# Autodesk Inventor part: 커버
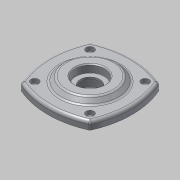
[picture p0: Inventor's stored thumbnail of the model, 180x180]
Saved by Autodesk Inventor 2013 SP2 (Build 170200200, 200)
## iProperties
Created: 2016-05
Part Number: 커버
Document SubType Name: Modeling
Designer: mduedu
Density: 2.71 g/cm^3
Material: 알루미늄 6061
Author: mduedu
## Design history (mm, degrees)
sketch "스케치1"
  geometry: L1 (0, 0)-(-35.355, 35.355); L2 (0, 0)-(0, 43); L3 (0, 0)-(43, 0); C1 r 25 at (0, 0); A1 r 85.579 centre (0, -42.579) between (35.355, 35.355) and (-35.355, 35.355); A2 r 85.579 centre (42.579, 0) between (-35.355, 35.355) and (-35.355, -35.355); A3 r 85.579 centre (0, 42.579) between (-35.355, -35.355) and (35.355, -35.355); A4 r 85.579 centre (-42.579, 0) between (35.355, -35.355) and (35.355, 35.355); 1 further point
  constraints: 10 point on circle, 6 end point, 5 centre point, 2 horizontal alignment, 2 vertical alignment, 1 coincident, 1 equal radius, 2 other
  dimensions: "d28" = 86 dimension on A4 A2; "d30" = 50 diameter of C1; "d31" = 45 deg angle of L2 L1; "d32" = 100 distance of A3.end L1.end
extrude "돌출1" new body sketch "스케치1" distance "d0" = 8; taper "d1" = 0 deg
extrude "돌출2" join sketch "스케치1" distance "d2" = 12; taper "d3" = 0 deg
sketch "스케치2"
  geometry: C1 r 30 at (0, 0); 1 further point
  constraints: 1 centre point, 1 coincident
  dimensions: "d4" = 60 diameter of C1
extrude "돌출3" join sketch "스케치2" distance "d5" = 5; taper "d6" = -45 deg
sketch "스케치3"
  geometry: C1 r 1.621 at (-28.284, 28.284) reference; C2 r 1.621 at (28.284, 28.284) reference; C3 r 1.621 at (28.284, -28.284) reference; C4 r 1.621 at (-28.284, -28.284) reference; 1 further point
hole "구멍1" sketch "스케치3" at (28.284, 28.284), (-28.284, 28.284), (-28.284, -28.284), (28.284, -28.284) diameter "d7" = 4.5; stored, may be unused: countersink angle "d11" = 90 deg, drill point angle "d13" = 118 deg; dims "d8" = 6, "d9" = 8, "d10" = 4.4, "d12" = 8
fillet "모깎기1" dims "d14" = 3
sketch "스케치4"
  geometry: L1 (-23.757, 13)-(23.757, 13) reference; L2 (25, -12)-(-25, -12) reference; L3 (0, -12)-(0, 13); L4 (-20, -12)-(-20, 0); L5 (-20, 0)-(-15, 0); L6 (-15, 0)-(-15, 3); L7 (-15, 3)-(-10, 3); L8 (-10, 3)-(-10, 5); L9 (-10, 5)-(-15, 5); L10 (-15, 5)-(-15, 13); 1 further point
  constraints: 16 end point, 6 parallel, 2 midpoint, 2 point on line, 1 perpendicular
  dimensions: "d15" = 40 diameter of L4 L3; "d16" = 30 diameter of L10 L3; "d17" = 8 distance of L9.end L10.end; "d18" = 12 distance of L4.start L4.end; "d19" = 3 distance of L5.end L6.end; "d20" = 30 diameter of L6 L3; "d21" = 20 diameter of L8 L3
revolve "회전1" sketch "스케치4" stored, may be unused: angle "d22" = 90 deg
fillet "모깎기2" dims "d23" = 3
fillet "모깎기3" dims "d24" = 0.3
chamfer "모따기1" distance "d25" = 1; stored, may be unused: second distance "d26" = 2, angle "d27" = 45 deg
node "솔리드1"
node "참조2"
node "참조3"
node "참조4"
node "참조5"
